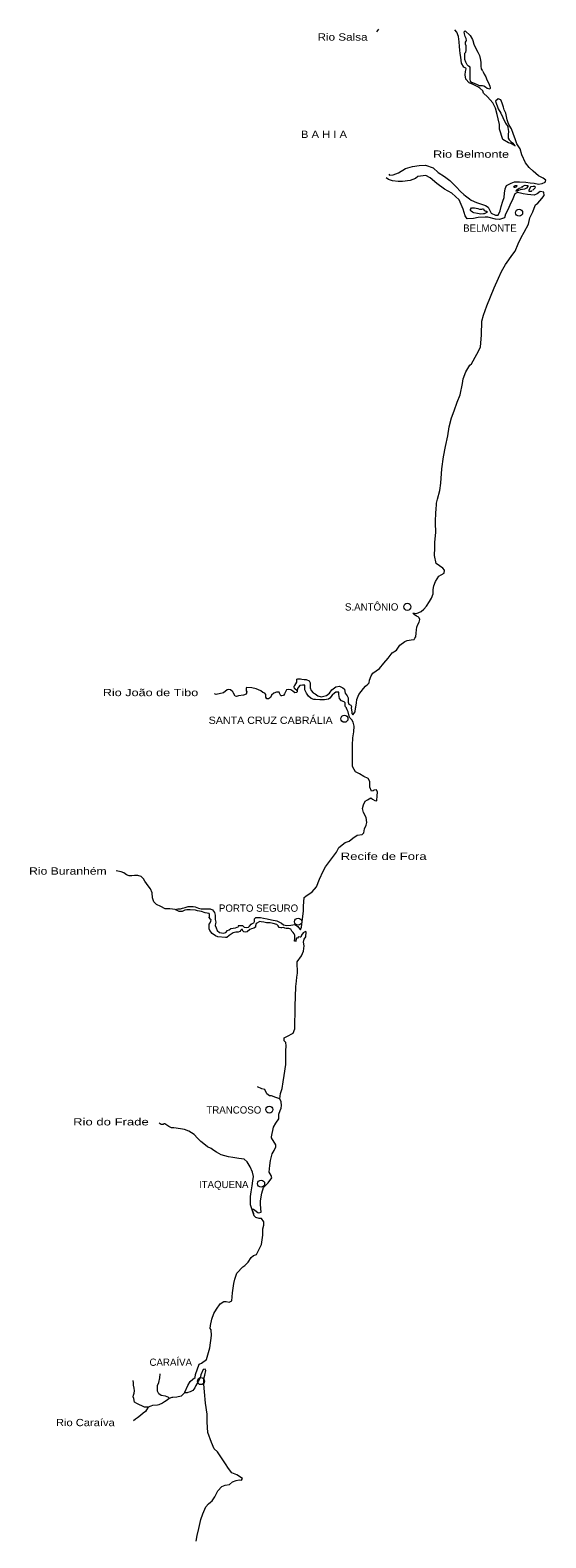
# Model space of a CAD drawing. Extents: x 47169 to 972804, y 7447977 to 9608469.
# Drawn here: x 468177 to 514758, y 8126563 to 8262604 of the extents above; entities that cross this region are included whole.
import ezdxf

# ---------------------------------------------------------------- set-up
doc = ezdxf.new("R2010")
doc.units = 0
doc.header["$LTSCALE"] = 270
doc.layers.add('1', color=7, linetype='Continuous', lineweight=13)
doc.layers.add('2', color=7, linetype='Continuous', lineweight=13)
doc.layers.add('3', color=7, linetype='Continuous')

msp = doc.modelspace()

# ---------------------------------------------------------------- linework, layer by layer
at = {"layer": '1'}
for points in [[(499626.8, 8262704.6), (499466.1, 8262450.2)], [(507522.3, 8259185.9), (507361.7, 8259263.4), (507147.5, 8259617.4), (507072.7, 8260159.4), (507008.5, 8260491.3), (506997.9, 8260801), (506965.9, 8261121.8), (506933.9, 8261553.2), (506869.7, 8262039.9), (506719.8, 8262427.1), (506527, 8262648.4)], [(509064.9, 8258897.7), (509182.6, 8258621.1), (509321.8, 8258388.8), (509428.8, 8258123.3), (509568, 8257857.7), (509632.2, 8257713.9), (509707.1, 8257559), (509739.2, 8257404.2), (509739.2, 8257326.7), (509707, 8257282.5), (509449.9, 8257349), (509310.7, 8257470.7), (509150.1, 8257548.2), (509043, 8257592.5), (508968, 8257581.5), (508925.1, 8257581.5), (508764.4, 8257581.5), (508582.4, 8257670.1), (508368.2, 8257769.7), (508164.7, 8257847.2), (508057.5, 8257847.3), (507961.2, 8258002.2), (507918.4, 8258190.2), (507918.5, 8258455.7), (507918.5, 8258654.8), (507918.6, 8258887.1), (507918.7, 8259119.4), (507918.8, 8259274.2), (507768.8, 8259362.8), (507640.3, 8259473.4), (507522.5, 8259705.8), (507436.9, 8259960.2), (507426.2, 8260159.3), (507426.3, 8260358.4), (507437.1, 8260535.4), (507522.8, 8260623.9), (507565.7, 8260767.6), (507565.8, 8260977.8), (507544.5, 8261188), (507490.9, 8261342.9), (507491, 8261453.5), (507501.7, 8261508.8), (507544.6, 8261608.3), (507576.8, 8261685.7), (507566.1, 8261862.7), (507469.7, 8262039.7), (507394.8, 8262261), (507384.1, 8262438), (507469.9, 8262548.5), (507919.8, 8262128.1), (508123.2, 8261774), (508155.3, 8261663.4), (508262.3, 8261353.6), (508369.4, 8261055), (508604.9, 8260612.4), (508765.5, 8260313.7), (508829.7, 8260048.2), (508861.8, 8259904.4), (508893.8, 8259672.1), (508893.7, 8259340.2), (508925.7, 8259119), (509032.8, 8258930.9)], [(500580, 8249596.9), (500622.9, 8249519.5), (500954.8, 8249541.6), (501447.4, 8249718.5), (502079.3, 8250127.8), (502700.4, 8250293.6), (503300.1, 8250404.1), (503889.1, 8250415.1), (504585.1, 8250193.8), (505024.1, 8249762.3), (505613, 8249386), (506094.8, 8249031.9), (506651.4, 8248467.6), (507036.8, 8248047.2), (507347.2, 8247770.5), (507486.4, 8247648.8), (507871.8, 8247394.3), (508021.6, 8247261.5), (508503.4, 8247051.2), (508953, 8246896.1), (509317, 8246785.4), (509552.5, 8246619.3), (509648.8, 8246464.4), (509755.8, 8246198.9), (509830.7, 8246077.2), (510205.3, 8245900), (510462.3, 8245922), (510644.5, 8246287), (510730.3, 8246707.3), (510880.4, 8247160.7), (510977, 8247514.7), (511020, 8247890.7), (511095.2, 8248288.9), (511202.4, 8248587.5), (511609.4, 8248786.4), (511920, 8248930), (512369.7, 8248929.8), (512947.9, 8248874.2), (513333.4, 8248829.7), (513697.5, 8248785.2), (514104.3, 8248707.6), (514436.3, 8248762.7), (514693.4, 8248895.2), (514757.8, 8249061.1), (514511.6, 8249249.3), (514083.4, 8249470.8), (513601.7, 8249869.3), (513248.6, 8250212.4), (512906.1, 8250644), (512585.3, 8251352.2), (512446.3, 8251905.3), (512146.7, 8252347.9), (512029.1, 8252713), (511815.2, 8253288.3), (511654.8, 8253708.7), (511430, 8254040.7), (511365.9, 8254250.9), (511269.6, 8254505.4), (511194.8, 8254826.2), (511130.7, 8255113.8), (510991.5, 8255423.6), (510916.7, 8255655.9), (510809.7, 8256009.9), (510681.3, 8256308.7), (510456.5, 8256408.3), (510210, 8256198.2), (510434.6, 8255512.3), (510680.8, 8255114), (510884.1, 8254715.7), (511098.1, 8254206.8), (511312.1, 8253908), (511333.5, 8253830.6), (511376.2, 8253465.5), (511365.3, 8253177.9), (511365.2, 8252857.2), (511440, 8252713.3), (511589.9, 8252547.3), (511761.2, 8252392.4), (511932.4, 8252204.2), (511975.2, 8252160), (511589.8, 8252370.3), (511397.1, 8252447.9), (510872.4, 8252735.7), (510562.3, 8253665), (510562.5, 8254085.4), (510434.2, 8254616.4), (510359.4, 8255003.5), (510220.4, 8255556.7), (509974.2, 8256054.6), (509492.5, 8256574.7), (509128.4, 8256928.8), (509074.9, 8257116.8), (508796.5, 8257360.3), (508625.2, 8257493.1), (508196.7, 8257692.4), (507821.9, 8257836.3), (507532.7, 8258190.4), (507457.9, 8258566.5), (507500.8, 8258876.2), (507565.2, 8259108.4), (507522.3, 8259185.9)], [(513492.4, 8246042.1), (513578.1, 8246219), (513696.1, 8246528.7), (513814.1, 8246849.4), (514017.6, 8247004.1), (514221.2, 8247214.2), (514381.9, 8247413.2), (514617.7, 8247678.5), (514575, 8247988.3), (514232.4, 8248043.8), (513964.6, 8247833.8), (513707.5, 8247712.3), (513107.9, 8247790.1), (512701.1, 8247834.5), (512583.3, 8247856.7), (512197.9, 8247945.4), (511951.5, 8247846), (511780, 8247370.5), (511512, 8246806.5), (511308.4, 8246386.2), (511126.1, 8245999.2), (511008.2, 8245667.4), (510558.5, 8245512.7), (510215.9, 8245535), (509520, 8245734.4), (509273.8, 8245734.5), (508642, 8245690.5), (508213.8, 8245624.3), (507657, 8245580.3), (507464.4, 8245856.9), (507293.2, 8246454.3), (506940.2, 8247306.1), (506276.5, 8247881.5), (505602, 8248268.8), (504906.1, 8248766.8), (504306.5, 8249264.6), (503921.1, 8249497), (503192.9, 8249408.6), (502989.4, 8249209.5), (502507.5, 8249032.6), (501800.8, 8248944.2), (501404.6, 8248944.2), (500901.3, 8249021.7), (500547.9, 8249143.4), (500323, 8249287.2)], [(512091, 8248432.2), (511994.7, 8248399), (511930.4, 8248399.1), (511823.4, 8248465.5), (511866.2, 8248509.7), (511994.8, 8248576), (512059, 8248587.1), (512112.6, 8248598.1), (512134, 8248587), (512101.8, 8248476.4)], [(512583.6, 8248398.7), (512637.2, 8248487.2), (512733.6, 8248564.6), (512872.9, 8248619.8), (513044.2, 8248597.6), (513119.1, 8248586.5), (513119.1, 8248509), (513001.2, 8248354.2), (512829.8, 8248243.7), (512637, 8248232.8), (512444.3, 8248199.7), (512272.9, 8248122.4), (512198, 8248089.2), (512069.5, 8248078.2), (512037.3, 8248100.4), (512133.8, 8248199.9), (512240.9, 8248277.2), (512348, 8248354.6), (512562.2, 8248398.7)], [(513525.8, 8248143.8), (513429.3, 8248055.3), (513247.3, 8248055.5), (513247.4, 8248177.1), (513333.1, 8248365.1), (513440.3, 8248486.7), (513611.7, 8248541.9), (513772.3, 8248530.8), (513783, 8248475.5), (513772.2, 8248331.7), (513697.2, 8248276.4), (513568.6, 8248176.9)], [(497180.9, 8201434.2), (497223.7, 8201091.3), (497223.7, 8200947.5), (497330.5, 8200836.9), (497544.2, 8201102.4), (497565.5, 8201412.1), (497597.6, 8201522.8), (497651, 8201898.9), (497683, 8202219.7), (497853.9, 8202673.2), (498281.3, 8203215.3), (498452.3, 8203414.4), (498687.4, 8203602.5), (498783.5, 8203724.2), (498826.3, 8203967.5), (498975.9, 8204343.6), (499114.8, 8204598.1), (499734.6, 8204996.3), (500119.4, 8205472), (500504.1, 8205925.5), (500888.9, 8206412.2), (501263, 8206655.5), (501572.9, 8207120.1), (502011.2, 8207440.9), (502235.6, 8207540.4), (502599, 8207584.6), (502866.2, 8207628.8), (502930.4, 8207750.5), (503015.9, 8207861.1), (503037.3, 8208204), (503080.1, 8208502.7), (503112.2, 8208735), (503187.1, 8208967.3), (503315.4, 8209199.6), (503368.9, 8209431.9), (503326.1, 8209575.7), (503219.3, 8209653.1), (503069.6, 8209741.6), (502877.2, 8209863.3), (502738.3, 8210007.2), (502898.6, 8210007.1), (503080.3, 8209973.9), (503497.3, 8210161.9), (503732.5, 8210361), (503978.4, 8210637.5), (504235, 8211046.7), (504438.2, 8211356.4), (504577.2, 8211743.5), (504577.3, 8212130.7), (504641.5, 8212473.6), (504780.6, 8212860.8), (505080, 8213336.4), (505315.3, 8213446.9), (505582.6, 8213601.7), (505593.4, 8213878.2), (505443.7, 8214055.3), (504855.8, 8214486.8), (504695.5, 8215205.9), (504717.1, 8215891.7), (504717.2, 8216367.3), (504824.3, 8217296.5), (504792.4, 8218126.2), (504824.7, 8219210.2), (504856.8, 8219276.5), (504867.7, 8219929.2), (504964, 8220294.2), (505178.1, 8221057.4), (505285.2, 8221721.1), (505360.4, 8223026.4), (505521.1, 8224110.4), (505692.4, 8225028.4), (505906.6, 8225990.8), (506024.5, 8226798.2), (506228, 8227627.8), (506474.2, 8228269.3), (506741.9, 8229032.5), (507031, 8229685), (507234.6, 8230713.7), (507277.6, 8231134), (507523.9, 8231764.4), (507877.2, 8232372.7), (508037.7, 8232505.4), (508508.9, 8233379.1), (508851.5, 8234009.5), (508948.3, 8235126.6), (508959.5, 8236332.4), (509120.2, 8236874.3), (509431, 8237737), (509752.4, 8238533.3), (510095.3, 8239351.7), (510491.7, 8240225.4), (510738.2, 8240822.6), (511113.2, 8241464), (511788, 8242381.7), (511991.6, 8242669.2), (512248.9, 8243310.6), (512516.9, 8243896.8), (512795.5, 8244372.2), (513181.3, 8245102.1), (513320.8, 8245666.1), (513492.4, 8246042.1)], [(492307.9, 8203003.8), (492286.5, 8202937.4), (492275.9, 8202826.8), (492072.8, 8202815.7), (491891.1, 8202959.4), (491709.4, 8203092.1), (491538.4, 8203114.2), (491324.7, 8203069.8), (491260.6, 8202970.2), (491153.9, 8202704.7), (491057.8, 8202571.9), (490908.2, 8202538.7), (490812, 8202538.7), (490705, 8202770.9), (490662.3, 8202881.5), (490427.2, 8202881.4), (490192.1, 8202781.7), (489978.5, 8202604.7), (489871.7, 8202383.4), (489700.8, 8202272.7), (489561.9, 8202272.6), (489476.3, 8202427.4), (489454.9, 8202648.7), (489380, 8202792.4), (489209, 8202836.6), (489027.2, 8203002.4), (488578.4, 8203157.1), (488193.6, 8203267.5), (487755.4, 8203300.4), (487702, 8203256.1), (487680.8, 8202990.7), (487755.7, 8202913.2), (487702.4, 8202680.9), (487456.6, 8202603.4), (486986.5, 8202525.7), (486826.2, 8202492.4), (486698, 8202514.4), (486548.2, 8202779.8), (486484, 8202912.5), (486280.9, 8203089.4), (486077.8, 8203111.4), (485971, 8203067), (485629.2, 8202801.3), (484988.2, 8202668.2), (484817.1, 8202712.3)], [(496913.8, 8201091.2), (496796.2, 8201290.3), (496764.2, 8201434.1), (496742.8, 8201456.3), (496689.4, 8201511.6), (496657.3, 8201533.7), (496635.9, 8201633.2), (496635.9, 8201799.2), (496625.2, 8201909.8), (496529, 8201987.2), (496293.9, 8202086.7), (496112.2, 8202285.8), (496069.4, 8202661.9), (496069.4, 8202861), (495973.2, 8202872.1), (495866.3, 8202872), (495802.2, 8202861), (495663.3, 8202794.6), (495449.6, 8202595.4), (495236, 8202318.8), (495129.1, 8202252.4), (494776.5, 8202163.9), (494327.7, 8202163.7), (493953.7, 8202196.8), (493814.8, 8202207.9), (493569, 8202307.3), (493312.5, 8202506.4), (493141.4, 8202782.9), (493002.4, 8203081.5), (493002.3, 8203313.8), (493002.3, 8203501.8), (492938.2, 8203501.8), (492767.2, 8203501.8), (492542.8, 8203479.6), (492403.9, 8203313.6), (492318.5, 8203191.9), (492307.9, 8203003.8), (492062, 8203191.8), (492019.2, 8203324.5), (492019.2, 8203402), (492072.6, 8203479.4), (492264.8, 8203778.1), (492264.8, 8203933), (492275.4, 8204054.7), (492350.2, 8204076.8), (492596, 8204076.9), (492724.3, 8204043.8), (492927.3, 8204021.7), (493119.7, 8204021.8), (493386.9, 8203889.1), (493461.7, 8203701.1), (493461.8, 8203502), (493461.9, 8203269.7), (493558.1, 8203015.3), (493739.8, 8202816.2), (493921.5, 8202705.7), (494167.3, 8202539.8), (494466.6, 8202451.4), (494947.4, 8202584.2), (495214.5, 8202794.5), (495438.8, 8203071.1), (495802.1, 8203336.6), (496133.4, 8203403.1), (496421.9, 8203259.3), (496571.6, 8203137.7), (496603.7, 8202916.4), (496625, 8202783.7), (496806.7, 8202551.4), (496902.9, 8202363.4), (496913.7, 8202164.2), (496913.7, 8201954.1), (496956.4, 8201788.2), (497127.4, 8201688.6), (497191.5, 8201589.1), (497180.9, 8201434.2)], [(491728.2, 8181853.1), (492080.5, 8181908.5), (492358.1, 8181731.6), (492422.2, 8181643.2), (492582.4, 8181433), (492699.7, 8181665.4), (492859.4, 8183147.8), (492859.2, 8183546), (492933.7, 8184342.5), (493072.5, 8184453.2), (493638.2, 8184862.6), (494054.5, 8185316.3), (494299.9, 8186002.2), (494641.4, 8186710.2), (494865.6, 8187097.5), (495388.7, 8187827.7), (495858.4, 8188436.2), (496050.5, 8188867.7), (496637.8, 8189299.2), (496990.2, 8189432), (497321.2, 8189708.6), (497705.7, 8189952), (498175.6, 8190018.4), (498303.7, 8190184.3), (498367.8, 8190549.4), (498538.6, 8190859.1), (498592, 8191113.5), (498517.2, 8191567.1), (498271.5, 8191998.5), (498207.4, 8192374.6), (498292.8, 8192706.5), (498442.3, 8193027.3), (498656, 8193149), (498933.7, 8193348.1), (499104.6, 8193226.4), (499307.5, 8193093.7), (499457, 8193060.5), (499489.1, 8193104.8), (499531.8, 8193503), (499563.9, 8193845.9), (499446.3, 8194067.1), (499254.1, 8194033.9), (499168.6, 8193956.5), (498997.7, 8193945.4), (498858.8, 8194299.4), (498858.8, 8194797.2), (498719.9, 8195073.7), (498314, 8195261.8), (497918.7, 8195494), (497576.9, 8195671), (497438, 8195903.3), (497299.1, 8196168.7), (497288.3, 8196744), (497288.2, 8197263.9), (497288.2, 8198093.5), (497330.8, 8198746.2), (497405.5, 8199288.2), (497437.5, 8199797.1), (497362.7, 8200151), (497234.4, 8200383.3), (497074.2, 8200527.1), (496978, 8200715.2), (496913.8, 8201091.2)], [(481286.2, 8183262.5), (480784.3, 8183306.3), (480378.6, 8183328.1), (479994.1, 8183515.8), (479577.5, 8183725.6), (479353.1, 8183946.6), (479224.6, 8184322.6), (479192.2, 8184754), (479053, 8185130), (478839.2, 8185406.3), (478529.1, 8185815.3), (478422.2, 8186014.3), (478208.4, 8186224.3), (477898.6, 8186323.5), (477610.3, 8186323.2), (477364.8, 8186289.8), (477119.2, 8186289.5), (476894.8, 8186388.9), (476649, 8186554.5), (476392.7, 8186664.9), (475944.1, 8186752.9)], [(488386.8, 8181586), (488173.4, 8181519.6), (488024, 8181453.1), (487778.5, 8181253.9), (487586.4, 8181209.5), (487479.6, 8181242.6), (487394.2, 8181331.1), (487362.1, 8181441.7), (487255.3, 8181441.6), (487202, 8181408.4), (487127.3, 8181286.7), (487116.6, 8181275.6), (486956.5, 8181220.2), (486753.7, 8181220.1), (486508.2, 8181164.6), (486433.5, 8181098.2), (486156.1, 8180898.9), (485942.7, 8180743.9), (485814.6, 8180743.8), (485142, 8180787.6), (484907.1, 8180887), (484608.1, 8181097), (484415.7, 8181351.3), (484340.9, 8181517.1), (484340.7, 8181738.4), (484340.6, 8181926.4), (484436.5, 8182070.3), (484511.2, 8182192), (484521.8, 8182313.7), (484468.3, 8182402.2), (484340.1, 8182545.9), (484382.8, 8182634.4), (484382.6, 8182822.5), (484339.9, 8182888.8), (483998.2, 8182966), (483645.8, 8183076.4), (483304.1, 8183153.5), (483111.9, 8183186.6), (482642.1, 8183230.5), (482321.8, 8183230.2), (482151, 8183196.9), (481905.5, 8183075), (481628, 8183074.8), (481457.1, 8183174.2), (481286.2, 8183262.5), (481510.3, 8183307), (481755.9, 8183307.2), (481937.3, 8183373.7), (482182.8, 8183429.2), (482460.3, 8183540), (482887.4, 8183540.4), (483090.3, 8183507.4), (483389.3, 8183385.9), (483634.9, 8183319.7), (483965.9, 8183308.9), (484435.7, 8183309.3), (484659.9, 8183243), (484830.9, 8182999.8), (484895.2, 8182734.4), (484895.4, 8182358.2), (484938.3, 8182114.9), (484906.4, 8181982.1), (484874.4, 8181816.2), (484992, 8181595), (485077.6, 8181362.8), (485280.5, 8181197), (485632.9, 8181119.8), (485846.3, 8181175.2), (486006.4, 8181352.4), (486155.8, 8181429.9), (486315.8, 8181540.6), (486508, 8181585), (486710.8, 8181596.2), (487020.3, 8181718), (486988.2, 8181784.4), (486977.5, 8181828.6), (487169.7, 8181828.7), (487361.9, 8181828.9), (487447.3, 8181740.4), (487511.4, 8181663), (487692.9, 8181641), (487885, 8181674.3), (487991.8, 8181751.8), (488130.4, 8181939.9), (488215.8, 8181984.2), (488386.6, 8182050.7), (488439.9, 8182172.4), (488439.8, 8182294.1), (488450.5, 8182404.7), (488557.2, 8182526.4), (488824, 8182537.6), (488994.9, 8182537.7), (489251.1, 8182482.5), (489571.4, 8182405.3), (489977.2, 8182328), (490457.6, 8182228.7), (490756.6, 8182096.1), (490884.7, 8182018.7), (491066.3, 8181886), (491365.2, 8181808.7), (491728.2, 8181853.1)], [(492411.8, 8180780.3), (492315.8, 8180658.6), (492241, 8180658.6), (492177, 8180470.5), (492198.4, 8180393.1), (492145, 8180393), (492059.7, 8180415.1), (492059.6, 8180470.5), (492070.3, 8180603.2), (492070.2, 8180736), (492080.8, 8180890.8), (492080.8, 8180957.2), (492038, 8181078.9), (491920.6, 8181189.4), (491824.5, 8181300), (491717.6, 8181499.1), (491546.8, 8181543.3), (491376, 8181543.2), (491312, 8181543.2), (491194.5, 8181565.3), (491130.4, 8181620.5), (491023.7, 8181642.6), (490916.9, 8181620.5), (490810.2, 8181620.4), (490682, 8181642.5), (490575.2, 8181797.3), (490468.4, 8181918.9), (490116.1, 8181996.2), (489849.2, 8182062.5), (489528.9, 8182062.3), (489294, 8182128.6), (489048.4, 8182150.6), (488909.7, 8182172.6), (488589.5, 8181995.5), (488546.9, 8181785.3), (488525.6, 8181663.6), (488386.8, 8181586)], [(488417.9, 8155622.2), (488392.2, 8155814.3), (488267.1, 8156109.7), (488237.6, 8156242.7), (488357.9, 8156231.4), (488485.9, 8156131.9), (488742, 8155910.8), (488837.9, 8155888.7), (489040.5, 8155944.2), (488986.8, 8156630), (488986.6, 8156984), (489092.9, 8157658.9), (489263.3, 8158167.8), (489679, 8158588.4), (489998.7, 8159053.2), (489945.3, 8159263.3), (489774.5, 8159550.9), (489838.2, 8160159.3), (489891.3, 8160624), (490029.7, 8161221.4), (490221.5, 8161509.1), (490360, 8161830), (490359.9, 8162029.1), (489986.3, 8162670.5), (489965, 8162747.9), (490156.5, 8163633), (490380.4, 8163987.1), (490646.9, 8164374.4), (490646.7, 8164805.8), (490753.2, 8165126.7), (490859.8, 8165336.9), (490881, 8165569.2), (490859.5, 8165912.2), (490742.1, 8166177.6), (490784.6, 8166642.2), (490955.1, 8167095.9), (491018.8, 8167715.4), (491135.9, 8168290.6), (491274.2, 8169286.3), (491263.3, 8169861.5), (491263.1, 8170492.1), (491305.5, 8170956.7), (491262.8, 8171255.4), (491134.6, 8171410.2), (491134.5, 8171686.7), (491347.9, 8171808.5), (491945.3, 8172096.4), (492073.2, 8172483.6), (492073.1, 8172881.8), (492104.7, 8174076.5), (492115.2, 8174563.3), (492136.2, 8175370.8), (492178.6, 8176300.1), (492221.1, 8176797.9), (492253, 8177151.9), (492316.9, 8177505.9), (492305.9, 8178523.6), (492700.6, 8179076.9), (492860.6, 8179508.3), (492913.8, 8179973), (492860.3, 8180304.8), (492934.9, 8180581.4), (493073.6, 8180802.7), (493116.2, 8181234.1), (493041.5, 8181278.3), (492838.7, 8181167.6), (492700, 8180935.3), (492625.3, 8180769.3), (492561.2, 8180769.3), (492411.8, 8180780.3)], [(490742.1, 8166177.6), (490379.3, 8166288.1), (489963.2, 8166431.7), (489803.2, 8166453.7), (489557.7, 8166641.7), (489386.9, 8167017.7), (489109.4, 8167083.9), (488704, 8167249.7)], [(488187.3, 8156242.4), (488091.8, 8156609.8), (488069.4, 8157359.6), (488143.8, 8157791.1), (488239.5, 8158322.1), (488292.5, 8158775.7), (488356.3, 8159174), (488249.5, 8159550.1), (488035.9, 8160025.6), (487769, 8160501.2), (487512.9, 8160733.3), (487022.3, 8160788.3), (486499.6, 8160887.6), (486083.6, 8160953.7), (485432.9, 8161130.2), (485016.8, 8161351.2), (484771.4, 8161528), (484515.3, 8161682.7), (484184.6, 8161837.3), (483853.7, 8162102.6), (483586.9, 8162312.6), (483298.7, 8162622.1), (482989.1, 8162953.7), (482519.5, 8163263.1), (482114.1, 8163406.5), (481751.4, 8163461.6), (481154, 8163549.5), (480951.3, 8163571.5), (480705.9, 8163670.8), (480524.4, 8163792.3), (480353.7, 8163913.9), (480279, 8163913.8), (480204.4, 8163869.5), (480119, 8163858.4), (480001.7, 8163858.2), (479830.9, 8163968.7)], [(489201.2, 8154439.8), (489297, 8154771.7), (489296.8, 8155081.4), (489062.1, 8155368.9), (488870.2, 8155391), (488560.9, 8155468.2), (488417.9, 8155622.2), (488187.3, 8156242.4)], [(483167.7, 8126248.5), (483273.7, 8126779.6), (483401, 8127410.3), (483581.4, 8128218), (483783.3, 8128716), (484059.7, 8129357.8), (484272.5, 8129645.6), (484453.4, 8129778.5), (484623.7, 8129911.4), (484857.8, 8130265.6), (485134.3, 8130807.8), (485485.5, 8131206.3), (485794.2, 8131328.2), (486177.6, 8131383.8), (486465, 8131616.3), (486795.1, 8131738.2), (487050.7, 8131804.7), (487253.1, 8131771.7), (487359.5, 8131926.6), (486848.1, 8132236), (486390, 8132423.8), (486102.1, 8132810.8), (485835.5, 8133253.1), (485451.7, 8133795), (485099.8, 8134336.8), (484812, 8134591), (484545.3, 8135177.1), (484235.7, 8136073), (484160.5, 8137013.2), (484159.9, 8137721.2), (484020.7, 8138727.8), (483924, 8139723.4), (483870.2, 8140442.4), (483869.8, 8140907), (483944.2, 8141227.9), (484050.4, 8141648.3), (483986.4, 8141792.1), (483805.3, 8141747.7), (483592.5, 8141260.8), (483539.5, 8140995.3), (483347.9, 8140685.4), (483156.4, 8140320.1), (483050, 8140098.8), (482869.1, 8139866.3), (482634.8, 8139744.5), (482421.8, 8139666.9), (482357.9, 8139644.7), (482283.3, 8139644.6), (482112.8, 8139644.5), (482144.7, 8139710.9), (482431.9, 8140297.4), (482623.4, 8140662.7), (482878.9, 8140895.2), (483070.6, 8141028.1), (483102.4, 8141293.6), (483453.2, 8142245.3), (483645, 8142333.9), (484113.6, 8142644), (484421.9, 8143695.2), (484570.2, 8144834.7), (484537.9, 8145343.6), (484441.9, 8145454.1), (484463, 8145708.6), (484579.8, 8146306), (484771.3, 8146792.9), (485016.1, 8147191.4), (485335.6, 8147678.3), (485676.5, 8147888.7), (485879, 8147888.9), (486145.5, 8147833.7), (486379.9, 8147955.6), (486454.1, 8148685.7), (486560.1, 8149504.4), (486666.5, 8149891.7), (486858, 8150433.9), (487380, 8151009.4), (487582.5, 8151131.2), (487880.8, 8151441.2), (488147.1, 8151850.6), (488360.2, 8152049.9), (488626.7, 8152116.4), (489063.3, 8153045.8), (489190.8, 8153886.7), (489201.2, 8154439.8)], [(482112.8, 8139644.5), (481825.4, 8139356.6), (481441.9, 8139256.7), (481058.4, 8139234.2), (480973.1, 8139212), (480728.2, 8139134.4), (480568.5, 8138979.4), (480302.3, 8138824.2), (480121.3, 8138702.4), (479791.1, 8138558.2), (479684.6, 8138547.1), (479226.5, 8138491.3), (479088.1, 8138458), (478832.5, 8138358.2), (478502.2, 8138357.8), (478385, 8138413), (477937.3, 8138622.8), (477809.3, 8138700.1), (477617.4, 8138810.5), (477553.2, 8139142.3), (477489.1, 8139297.1), (477510.2, 8139452), (477563.3, 8139606.9), (477616.4, 8139839.3), (477562.8, 8140071.6), (477509.2, 8140348.1), (477509, 8140536.1), (477476.9, 8140757.3)], [(480728.2, 8139134.4), (480706.8, 8139211.8), (480408.3, 8139344.3), (480024.7, 8139421.4), (479811.5, 8139542.8), (479683.4, 8139808.2), (479683.1, 8140095.8), (479682.9, 8140306), (479810.5, 8140571.7), (479906, 8141014.2), (479927, 8141357.2)], [(478832.5, 8138358.2), (478694.2, 8138125.7), (478598.5, 8137959.7), (478396.2, 8137804.6), (478151.4, 8137605.2), (477874.6, 8137394.7), (477693.7, 8137261.8), (477523.4, 8137117.8)]]:
    msp.add_lwpolyline(points, dxfattribs=at)
msp.add_lwpolyline([(508256.8, 8246122.1), (508128.3, 8246188.5), (508010.6, 8246277), (507946.3, 8246343.4), (507946.4, 8246431.9), (508042.8, 8246564.6), (508182, 8246564.6), (508321.2, 8246564.5), (508599.5, 8246498), (508749.4, 8246453.7), (508888.6, 8246453.7), (508985, 8246453.6), (509070.6, 8246475.7), (509134.9, 8246475.7), (509156.3, 8246420.4), (509199, 8246320.8), (509263.3, 8246309.7), (509338.2, 8246276.5), (509413.2, 8246265.4), (509413.1, 8246165.9), (509316.7, 8246088.5), (509198.9, 8246044.3), (509124, 8246044.3), (508895.8, 8246004.7), (508580.3, 8246048.6)], close=True, dxfattribs=at)
at = {"layer": '2'}
for centre, radius in [((512336.1, 8246131.3), 321.2), ((502246.6, 8210571.4), 320.9), ((496561.3, 8200471.7), 320.3), ((492382.8, 8182161.8), 320.5), ((489782.5, 8165203.7), 320), ((489039.2, 8158521.7), 319.9), ((483603.6, 8140707.7), 319.4)]:
    msp.add_circle(centre, radius, dxfattribs=at)

# ---------------------------------------------------------------- texts
at = {"layer": '3'}
for s, height, width, p in [('Rio Salsa', 657.6, 1.2, (494136.2, 8261657.7)), ('B A H I A', 657.4, 1.15, (492637.9, 8252878)), ('Rio Belmonte', 657.3, 1.3, (504574.6, 8251089.7)), ('Rio João de Tibo', 655.9, 1.3, (474740.3, 8202509.3)), ('SANTA CRUZ CABRÁLIA', 655.8, 1.1, (484300.4, 8200005.3)), ('Recife de Fora', 655.4, 1.35, (496229, 8187734)), ('Rio Buranhém', 655.4, 1.25, (468086.7, 8186406.9)), ('Rio do Frade', 654.7, 1.35, (472058.4, 8163774.9)), ('Rio Caraíva', 653.9, 1.15, (470513.4, 8136640.3))]:
    msp.add_text(s, height=height, dxfattribs=dict(at, width=width)).set_placement(p)
for s, height, p in [('BELMONTE', 657.1, (507284.7, 8244417.9)), ('S.ANTÔNIO', 656.1, (496611, 8210234.8)), ('PORTO SEGURO', 655.3, (485228, 8183055.9)), ('TRANCOSO', 654.7, (484092.6, 8164847.8)), ('ITAQUENA', 654.5, (483424.5, 8158120.2)), ('CARAÍVA', 654, (478959.2, 8142085))]:
    msp.add_text(s, height=height, dxfattribs=at).set_placement(p)

doc.saveas('drawing.dxf')
